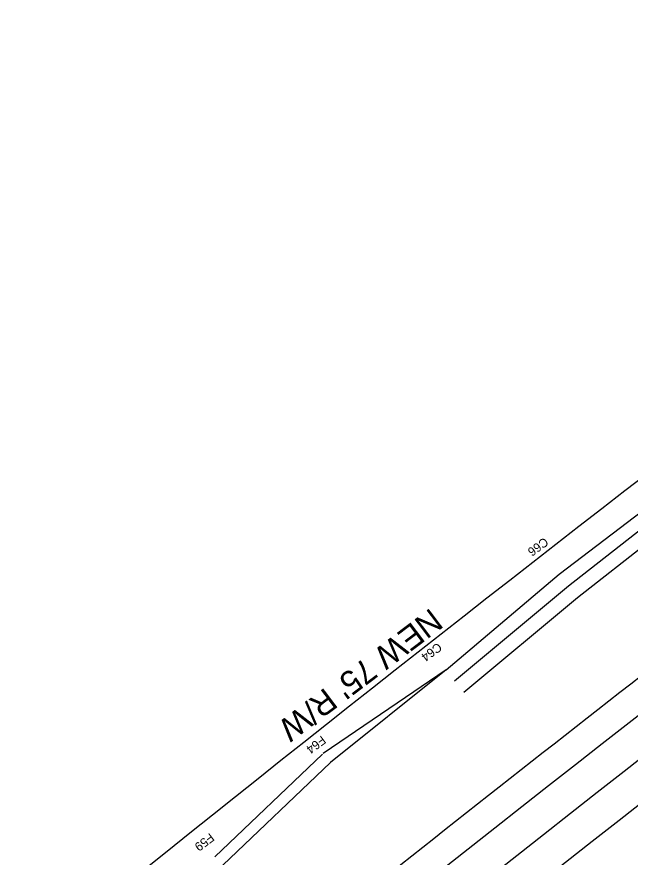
# Model space of a CAD drawing. Extents: x 1469024 to 1473560, y 1105695 to 1109739.
# Drawn here: x 1470653 to 1470861.2, y 1107470.7 to 1107756 of the extents above; entities that cross this region are included whole.
import ezdxf

# ---------------------------------------------------------------- set-up
doc = ezdxf.new("R2010")
doc.units = 0
for name, color, linetype in [('RD_HC_CL_Rel', 7, 'Continuous'), ('RD_PD_CstnLmt', 7, 'Continuous'), ('RD_PD_CstnLmt_TX', 7, 'Continuous'), ('RD_PD_DR_Ditch', 7, 'Continuous'), ('RD_PD_DR_ErosCtrl', 7, 'Continuous'), ('RD_PD_Final_TrvlWay', 7, 'Continuous'), ('RD_PD_GR', 7, 'Continuous'), ('RD_PD_RW', 7, 'Continuous'), ('RD_PD_RW_TX', 7, 'Continuous')]:
    doc.layers.add(name, color=color, linetype=linetype)

msp = doc.modelspace()

# ---------------------------------------------------------------- linework, layer by layer
at = {"layer": 'RD_HC_CL_Rel'}
msp.add_arc((1477943.58, 1098441.09), 11500, 126.41418, 130.102414, dxfattribs=at)
at = {"layer": 'RD_PD_CstnLmt'}
for p, q in [((1470837.12, 1107566.82), (1470877.09, 1107597.35)), ((1470798.71, 1107534.31), (1470837.12, 1107566.82)), ((1470798.71, 1107534.31), (1470759.49, 1107502.85)), ((1470759.49, 1107502.85), (1470722.99, 1107467.99))]:
    msp.add_line(p, q, dxfattribs=at)
at = {"layer": 'RD_PD_DR_Ditch'}
for p, q in [((1470840.22, 1107562.84), (1470879.75, 1107593.9)), ((1470843.29, 1107558.9), (1470882.8, 1107589.94)), ((1470801.6, 1107530.64), (1470840.22, 1107562.84)), ((1470804.69, 1107526.71), (1470843.29, 1107558.9))]:
    msp.add_line(p, q, dxfattribs=at)
at = {"layer": 'RD_PD_DR_ErosCtrl'}
for p, q in [((1470798.71, 1107534.31), (1470756.99, 1107505.97)), ((1470756.73, 1107505.74), (1470720.23, 1107470.89))]:
    msp.add_line(p, q, dxfattribs=at)
at = {"layer": 'RD_PD_Final_TrvlWay'}
for radius in [11512, 11488]:
    msp.add_arc((1477943.58, 1098441.09), radius, 126.41418, 130.102414, dxfattribs=at)
at = {"layer": 'RD_PD_GR'}
msp.add_arc((1477943.58, 1098441.09), 11522, 127.151906, 128.656189, dxfattribs=at)
at = {"layer": 'RD_PD_RW'}
msp.add_arc((1477943.58, 1098441.09), 11575, 126.41418, 129.547337, dxfattribs=at)

# ---------------------------------------------------------------- texts
at = {"layer": 'RD_PD_CstnLmt_TX'}
for s, rotation, p in [('C66', 216.2301, (1470832.01, 1107579.46)), ('C64', 216.4792, (1470795.87, 1107543.72)), ('F64', 216.7283, (1470756.47, 1107512.14)), ('F59', 216.9774, (1470718.58, 1107479.06))]:
    msp.add_text(s, height=3, rotation=rotation, dxfattribs=at).set_placement(p)
at = {"layer": 'RD_PD_RW_TX'}
msp.add_text("NEW 75' R/W", height=8, rotation=217.0793, dxfattribs=at).set_placement((1470793.48, 1107555.57))

doc.saveas('drawing.dxf')
